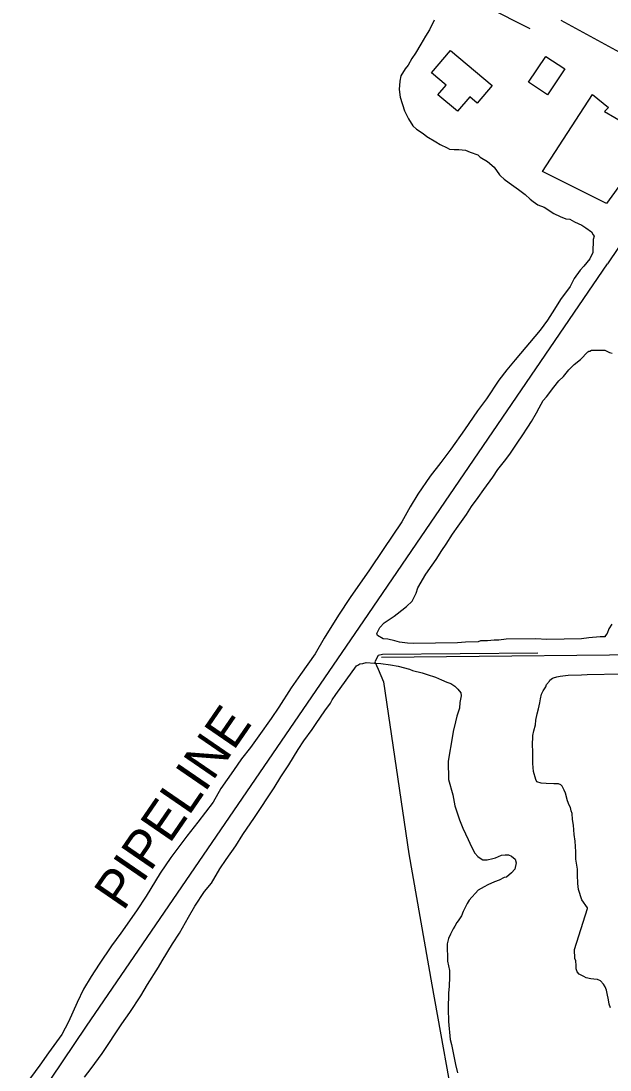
# Model space of a CAD drawing. Extents: x 3297716 to 3335574, y 688621 to 713991.
# Drawn here: x 3307126 to 3308413, y 705686 to 707980 of the extents above; entities that cross this region are included whole.
import ezdxf

# ---------------------------------------------------------------- set-up
doc = ezdxf.new("R2010")
doc.units = 0
for name, color, linetype in [('V-BLDG-OTLN', 7, 'Continuous'), ('V-ROAD-CNTR', 7, 'Continuous'), ('V-SITE-VEGE', 7, 'Continuous'), ('V-TOPO-SHOR', 7, 'Continuous'), ('V-UTIL-IDEN', 7, 'Continuous'), ('V-UTIL-LINE', 7, 'Continuous')]:
    doc.layers.add(name, color=color, linetype=linetype)

msp = doc.modelspace()

# ---------------------------------------------------------------- linework, layer by layer
at = {"layer": 'V-BLDG-OTLN'}
for points in [[(3308023.1, 707866.1), (3308064.3, 707915.1), (3308155.1, 707838.8), (3308122.7, 707800.3), (3308106.4, 707814), (3308079.7, 707782.3), (3308036.7, 707818.4), (3308054.6, 707839.6)], [(3308235, 707845.9), (3308272.5, 707902.4), (3308313.8, 707875.1), (3308276.3, 707818.5)], [(3308405.4, 707580.5), (3308265.5, 707650.9), (3308374.6, 707819.3), (3308409.6, 707790.7), (3308401.1, 707782.1), (3308513.4, 707716.4), (3308490.7, 707681.2), (3308482, 707687)]]:
    msp.add_lwpolyline(points, close=True, dxfattribs=at)
at = {"layer": 'V-ROAD-CNTR'}
for points in [[(3308977.2, 707416), (3308954.6, 707416.9), (3308933.1, 707415), (3308913.2, 707415.5), (3308898.7, 707423), (3308889.2, 707431.1), (3308869.5, 707462.1), (3308859, 707500.7), (3308856.3, 707544.3), (3308844.5, 707597.6), (3308824.6, 707644.8), (3308800.7, 707682.6), (3308787.6, 707702.8), (3308772.6, 707720.7), (3308757.9, 707732.5), (3308739.1, 707746.5), (3308720.1, 707758.9), (3308529.7, 707861), (3308442.5, 707906.7), (3308306, 707981)], [(3309110.8, 706651.6), (3308746.6, 706600.4), (3308690.7, 706593.9), (3308625, 706595.9), (3307913.7, 706588.2)]]:
    msp.add_lwpolyline(points, dxfattribs=at)
at = {"layer": 'V-SITE-VEGE'}
for points in [[(3308028.3, 707981.3), (3308018.4, 707960.7), (3308009.4, 707946.3), (3307999.5, 707928.8), (3307987.5, 707909.2), (3307979.5, 707897.8), (3307971.6, 707883.4), (3307965.5, 707875.1), (3307955.6, 707859.6), (3307953.7, 707848.3), (3307951.9, 707829.9), (3307954.2, 707813.6), (3307963.9, 707783.1), (3307972.3, 707765.8), (3307981.8, 707750.6), (3307990.1, 707743.6), (3308004.5, 707733.6), (3308012.8, 707727.6), (3308032.4, 707715.6), (3308041.7, 707709.7), (3308057.1, 707702.7), (3308062.3, 707699.7), (3308072.5, 707698.9), (3308082.7, 707699), (3308097.1, 707697.2), (3308107.3, 707693.3), (3308123.8, 707687.4), (3308129, 707682.4), (3308145.5, 707672.4), (3308160, 707660.4), (3308171.5, 707643.2), (3308173.6, 707641.1), (3308181.9, 707634.1), (3308192.2, 707626.1), (3308212.9, 707611.1), (3308227.4, 707600.1), (3308238.7, 707590), (3308245, 707585), (3308255.3, 707578), (3308268.7, 707573.1)], [(3308268.7, 707573.1), (3308290.3, 707559.1), (3308303.7, 707552.2), (3308316.1, 707547.2), (3308325.3, 707546.4), (3308335.6, 707540.4), (3308351, 707533.5), (3308360.3, 707527.5), (3308372.7, 707518.5), (3308375.9, 707512.4), (3308378, 707509.3), (3308376, 707502.2), (3308375.5, 707473.5), (3308368.5, 707460.1), (3308355.5, 707443.6), (3308347.4, 707435.3), (3308334.4, 707416.7), (3308325.5, 707399.2), (3308304.5, 707371.2), (3308291.5, 707349.6), (3308276.5, 707325.8), (3308260.5, 707304.1), (3308205.3, 707238.9), (3308187.2, 707217.1), (3308170.2, 707194.4), (3308143.2, 707154.1), (3308123.2, 707127.2), (3308095.2, 707085.9), (3308065.2, 707043.6), (3308043.1, 707014.6), (3308020.1, 706984.6), (3307993.1, 706945.3), (3307976.1, 706917.5), (3307958.2, 706884.5), (3307917.2, 706824.6), (3307887.3, 706780.2), (3307845.3, 706719.2), (3307819.3, 706681), (3307788.4, 706630.4), (3307768.4, 706596.4), (3307736.4, 706550.9), (3307716.4, 706522), (3307689.5, 706479.7), (3307672.5, 706454.9), (3307645.5, 706416.7), (3307627.4, 706391.8), (3307607.4, 706367), (3307590.4, 706341.2), (3307562.4, 706301.9), (3307545.5, 706272), (3307512.4, 706228.6), (3307488.3, 706197.5), (3307453.3, 706151), (3307430.3, 706116.9), (3307399.4, 706066.4), (3307378.4, 706034.4), (3307344.4, 705985.8), (3307323.4, 705957.9), (3307296.4, 705917.6), (3307279.4, 705890.8), (3307262.5, 705862.9), (3307248.6, 705834.1), (3307229.8, 705791.9), (3307214.9, 705764), (3307185.9, 705723.7), (3307166.9, 705696.9), (3307136.8, 705655.5)], [(3308416.5, 706661.5), (3308410.6, 706651.2), (3308406.6, 706640.9), (3308402.6, 706635.8), (3308402.6, 706633.7), (3308391.4, 706633.5), (3308366.9, 706631.1), (3308350.6, 706628.8), (3308275, 706627.7), (3308250.4, 706629.3), (3308186, 706628.4), (3308169.7, 706626.1), (3308159.5, 706625.9), (3308145.2, 706624.7), (3308129.9, 706624.4), (3308124.8, 706622.3), (3308097.2, 706621.9), (3308079.8, 706620.6), (3307983.8, 706619.1), (3307970.5, 706619.9), (3307953.1, 706621.7), (3307942.8, 706624.6), (3307927.4, 706628.5), (3307917.2, 706629.3), (3307904.8, 706636.3), (3307903.7, 706640.4), (3307909.6, 706653.8), (3307919.7, 706664.1), (3307941, 706678.8), (3307948, 706684), (3307968.2, 706699.6), (3307980.3, 706711.1), (3307989.3, 706728.6), (3307993.2, 706740.9), (3308010.1, 706770.8), (3308024.1, 706790.4), (3308033.1, 706802.8), (3308045.1, 706822.5), (3308055.1, 706835.9), (3308069, 706857.6), (3308081, 706875.1), (3308099, 706901), (3308110, 706918.5), (3308125.1, 706938.2), (3308137.1, 706955.7), (3308157.1, 706982.6), (3308168.1, 706999.1), (3308185.1, 707020.9), (3308195.1, 707035.3), (3308211.1, 707059.1), (3308221.1, 707072.5), (3308233.1, 707092.1), (3308241.1, 707104.5), (3308252, 707123.1), (3308258, 707134.4), (3308267, 707149.9), (3308274, 707158.2), (3308290, 707178.9), (3308301, 707193.3), (3308311.1, 707202.7), (3308323.2, 707217.2), (3308334.2, 707228.6), (3308348.4, 707240.1), (3308364.5, 707256.7), (3308366.5, 707257.7), (3308368.5, 707257.7), (3308372.6, 707259.9), (3308401.2, 707260.3), (3308411.5, 707255.3), (3308417.7, 707253.4)], [(3307264.4, 705670.8), (3307279.4, 705689.4), (3307303.5, 705722.5), (3307346.4, 705787.5), (3307363.4, 705812.3), (3307387.4, 705848.5), (3307402.3, 705873.2), (3307426.3, 705911.4), (3307434.3, 705924.8), (3307457.2, 705962), (3307472.2, 705985.7), (3307492.1, 706020.8), (3307506, 706044.5), (3307527, 706076.5), (3307542, 706095.1), (3307560, 706126.1), (3307574, 706146.7), (3307595, 706176.7), (3307610.9, 706201.5), (3307635.9, 706238.7), (3307678.9, 706303.7), (3307693.9, 706327.4), (3307710.8, 706353.3), (3307731.8, 706387.3), (3307743.8, 706405.9), (3307761.8, 706430.7), (3307770.8, 706444.1), (3307789.8, 706472), (3307801.8, 706488.6), (3307805.8, 706495.8), (3307813.8, 706507.1), (3307858.8, 706570.2)], [(3307858.8, 706570.2), (3307861.8, 706571.3), (3307865.9, 706574.4), (3307873, 706575.5), (3307880.1, 706577.7), (3307898.6, 706575.9), (3307911.9, 706575.1), (3307933.4, 706572.4), (3307949.8, 706569.5), (3307974.4, 706562.8), (3307981.6, 706559.8), (3308002.1, 706555), (3308013.4, 706551.1), (3308031.9, 706545.2), (3308044.3, 706539.3), (3308056.6, 706534.4)], [(3308329.9, 706247.2), (3308327.7, 706253.3), (3308326.6, 706260.5), (3308323.4, 706265.5), (3308320.2, 706274.7), (3308315.9, 706292), (3308312.7, 706298.1), (3308308.5, 706307.2), (3308305.4, 706310.2), (3308300.2, 706312.2), (3308290, 706312.1), (3308273.7, 706312.8), (3308262.4, 706313.7), (3308253.2, 706316.6), (3308251, 706321.7), (3308245.7, 706339), (3308244.4, 706356.3), (3308243.9, 706384.9), (3308243.8, 706395.2), (3308244.4, 706417.7), (3308246.3, 706427.9), (3308250.2, 706441.3), (3308251.1, 706451.5), (3308253.9, 706464.8), (3308256.8, 706476.1), (3308259.7, 706489.4), (3308260.6, 706497.6), (3308263.5, 706507.9), (3308266.5, 706515.1), (3308272.5, 706524.4), (3308274.4, 706529.5), (3308280.4, 706536.8), (3308281.4, 706538.8), (3308287.5, 706543), (3308289.5, 706544.1), (3308296.7, 706546.2), (3308303.8, 706547.4), (3308321.1, 706549.7), (3308350.8, 706550.1), (3308363, 706551.3), (3308437.6, 706552.5)], [(3308056.6, 706534.4), (3308064.8, 706531.4), (3308074.1, 706525.4), (3308080.4, 706519.4), (3308086.6, 706511.3), (3308087.8, 706504.2), (3308084.9, 706489.8), (3308084.1, 706477.6), (3308078.2, 706460.1), (3308075.3, 706447.8), (3308070.5, 706426.2), (3308068.6, 706417), (3308059.3, 706361.7), (3308059.9, 706321.8), (3308069.6, 706288.2), (3308074.1, 706263.8), (3308083.7, 706233.2), (3308091.2, 706215), (3308102.8, 706190.6), (3308110.2, 706174.4), (3308117.6, 706160.2), (3308123.8, 706153.1), (3308131, 706148.1), (3308135.1, 706146.1), (3308144.3, 706146.3), (3308156.6, 706148.5), (3308162.7, 706150.6), (3308175.9, 706156), (3308184, 706157.1), (3308191.2, 706157.2), (3308197.4, 706154.2), (3308205.7, 706147.2), (3308207.8, 706139.1), (3308205, 706125.7), (3308197.9, 706117.4), (3308186.8, 706108.1), (3308181.7, 706107), (3308170.6, 706101.7), (3308160.4, 706097.5), (3308146.2, 706091.1), (3308138.1, 706086.9), (3308124.9, 706079.5), (3308118.9, 706073.3), (3308110.9, 706064), (3308104.8, 706057.8), (3308100.8, 706050.5), (3308097.9, 706044.4), (3308091.9, 706033), (3308088, 706023.8), (3308081, 706012.4), (3308078, 706009.3), (3308074, 706001.1), (3308070, 705994.9), (3308064, 705983.5), (3308060.1, 705974.3), (3308057.2, 705962), (3308057.8, 705924.2), (3308062.2, 705903.8), (3308062.4, 705889.5), (3308061.7, 705870), (3308059.9, 705854.7), (3308059.4, 705819.9), (3308059.8, 705792.3), (3308063.5, 705753.5), (3308066.7, 705742.3), (3308072.3, 705712.8), (3308075.6, 705698.5), (3308079.9, 705680.2)], [(3308414.1, 705822.3), (3308410.9, 705830.4), (3308409.7, 705839.6), (3308406.4, 705853.9), (3308405.3, 705861), (3308402.1, 705868.1), (3308398.9, 705874.2), (3308391.7, 705881.2), (3308385.5, 705884.2), (3308377.3, 705885.1), (3308371.2, 705886), (3308360.9, 705887.9), (3308355.8, 705890.9), (3308345.5, 705895.9), (3308341.3, 705900.9), (3308339.1, 705908), (3308339, 705915.2), (3308337.9, 705925.4), (3308335.7, 705930.5), (3308335.4, 705949.9), (3308363.7, 706039.2), (3308363.7, 706041.3), (3308351.1, 706058.5), (3308343.7, 706080.8), (3308342.4, 706094.1), (3308342.1, 706113.5), (3308341.9, 706125.8), (3308338.5, 706147.2), (3308338.3, 706163.6), (3308336.9, 706187), (3308334.6, 706201.3), (3308333.3, 706221.7), (3308331.1, 706234), (3308329.9, 706247.2)]]:
    msp.add_lwpolyline(points, dxfattribs=at)
at = {"layer": 'V-TOPO-SHOR'}
msp.add_line((3308143.9, 708010.5), (3308237.4, 707963.7), dxfattribs=at)
msp.add_lwpolyline([(3308254.8, 706597.4), (3307915.4, 706595), (3307906.1, 706592.7), (3307899.2, 706578.9), (3307906.1, 706562.7), (3307917.7, 706535), (3307973.1, 706158.7), (3308023.9, 705872.4), (3308079.3, 705560.7), (3308104.7, 705422.2), (3308116.2, 705369.1)], dxfattribs=at)
at = {"layer": 'V-UTIL-LINE'}
for points in [[(3310544.7, 708998.9), (3309154.8, 708242.8), (3308742.2, 707946.5), (3308407.2, 707448.9)], [(3306265.6, 703037.5), (3305889.4, 703776.7), (3305605.8, 704391.2), (3306617.9, 704815.4), (3307269.3, 705782.5), (3307875.3, 706668.1), (3308407.2, 707448.9)]]:
    msp.add_lwpolyline(points, dxfattribs=at)

# ---------------------------------------------------------------- texts
at = {"layer": 'V-UTIL-IDEN'}
msp.add_text('PIPELINE', height=83, rotation=55.5391, dxfattribs=at).set_placement((3307349.4, 706032))

doc.saveas('drawing.dxf')
